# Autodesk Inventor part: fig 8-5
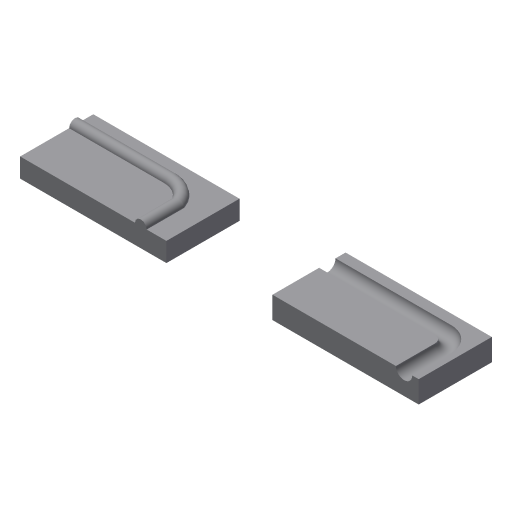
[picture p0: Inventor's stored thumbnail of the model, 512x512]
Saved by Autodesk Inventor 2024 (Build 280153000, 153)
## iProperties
Created: 2009-04
Part Number: fig 8-5
Document SubType Name: Modeling
Designer: Sham
Density: 1 g/cm^3
Material: Generic
Appearance: Default
Author: Sham
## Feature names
1. Extrusion1
2. Sweep5
3. Extrusion2
4. Sweep6
## Parameters: d0 = 6 mm, d1 = 0, d6 = 0, d7 = 5.25 mm, d8 = 0, d9 = 0, d10 = 0, d11 = 0
